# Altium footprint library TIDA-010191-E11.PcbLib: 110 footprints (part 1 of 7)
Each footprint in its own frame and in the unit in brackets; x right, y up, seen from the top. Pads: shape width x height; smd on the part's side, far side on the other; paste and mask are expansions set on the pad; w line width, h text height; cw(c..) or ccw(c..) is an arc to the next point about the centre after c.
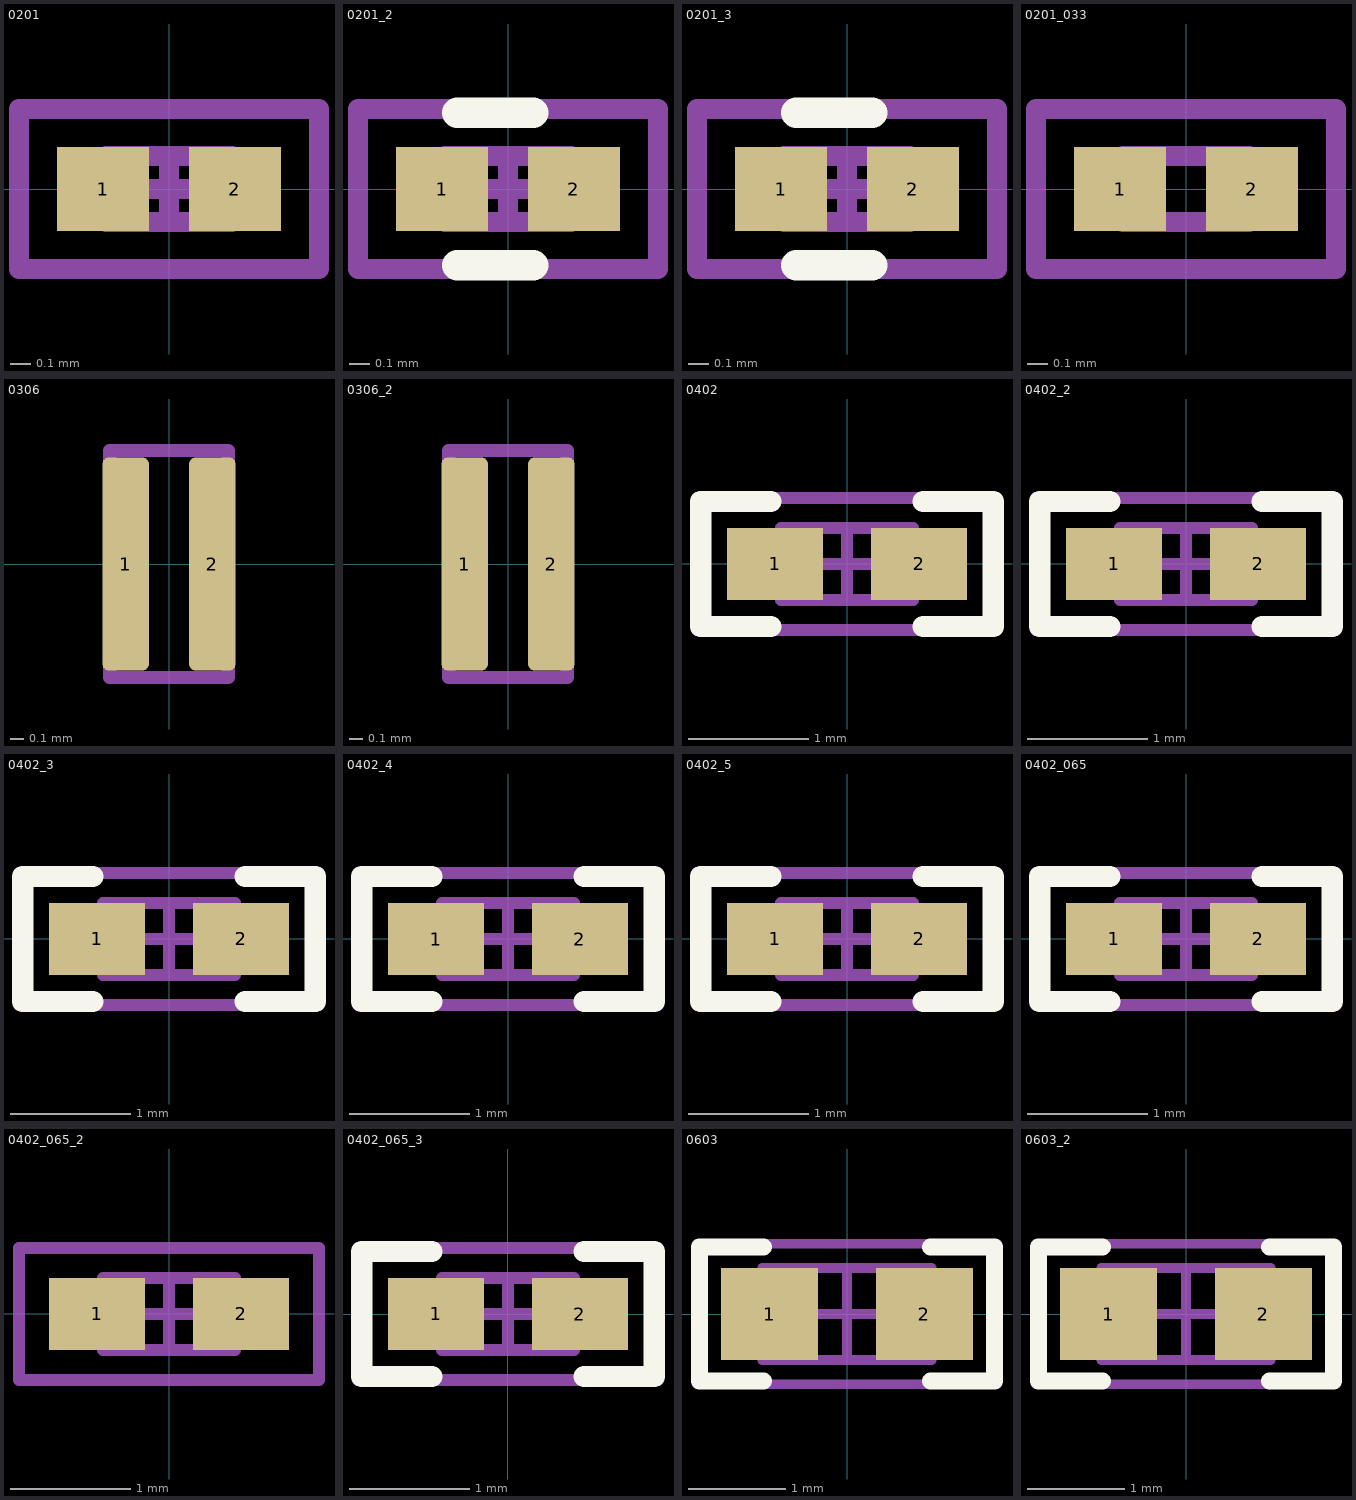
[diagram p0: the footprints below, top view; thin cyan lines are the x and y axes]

## 0201 [mm] "Data from Kemet datasheet CC101_COM dated 7/28/11"
height 0.26
pads (2):
  rect 0.46x0.42 smd mask+0.048: 1(-0.33,0) 2(0.33,0)
Mechanical 5:
  lines w0.1: -0.75,-0.4 -0.75,0.4 0.75,0.4 0.75,-0.4 -0.75,-0.4
  text ".Designator" at -0.66,-0.178 h0.36
Mechanical 13:
  lines w0.1: -0.215,-0.165 -0.215,0.165 ; 0.215,-0.165 0.215,0.165 ; -0.315,-0.165 0.315,-0.165 0.315,0.165 -0.315,0.165 -0.315,-0.165
Mechanical 15:
  lines w0.1: -0.165,0 0.165,0 ; 0,-0.165 0,0.165 ; -0.75,-0.4 0.75,-0.4 0.75,0.4 -0.75,0.4 -0.75,-0.4
3D body: height 0.26, standoff 0, extent 0.216,-0.164 0.314,0.164
3D body: height 0.26, standoff 0, extent -0.214,-0.164 0.214,0.164
3D body: height 0.26, standoff 0, extent -0.314,-0.164 -0.216,0.164

## 0201_2 [mm]
pads (2):
  rect 0.46x0.42 smd mask+0.048: 1(-0.33,0) 2(0.33,0)
Top Overlay:
  lines w0.152: -0.254,-0.381 0.127,-0.381 ; -0.254,0.381 0.127,0.381
Mechanical 5:
  lines w0.1: -0.75,-0.4 0.75,-0.4 0.75,0.4 -0.75,0.4 -0.75,-0.4
  text ".Designator" at 0.736,1.236 h0.64
Mechanical 13:
  lines w0.1: -0.215,-0.165 -0.215,0.165 ; 0.215,-0.165 0.215,0.165 ; -0.315,-0.165 -0.315,0.165 0.315,0.165 0.315,-0.165 -0.315,-0.165
Mechanical 15:
  lines w0.1: -0.165,0 0.165,0 ; 0,-0.165 0,0.165 ; -0.75,-0.4 -0.75,0.4 0.75,0.4 0.75,-0.4 -0.75,-0.4
3D body: height 0.26, standoff 0, extent -0.314,-0.164 -0.216,0.164
3D body: height 0.26, standoff 0, extent -0.214,-0.164 0.214,0.164
3D body: height 0.26, standoff 0, extent 0.216,-0.164 0.314,0.164

## 0201_3 [mm]
pads (2):
  rect 0.46x0.42 smd mask+0.048: 1(-0.33,0) 2(0.33,0)
Top Overlay:
  lines w0.152: -0.254,-0.381 0.127,-0.381 ; -0.254,0.381 0.127,0.381
Mechanical 5:
  lines w0.1: -0.75,-0.4 0.75,-0.4 0.75,0.4 -0.75,0.4 -0.75,-0.4
  text ".Designator" at -2.175,-0.278 h0.64
Mechanical 13:
  lines w0.1: -0.215,-0.165 -0.215,0.165 ; 0.215,-0.165 0.215,0.165 ; -0.315,-0.165 -0.315,0.165 0.315,0.165 0.315,-0.165 -0.315,-0.165
Mechanical 15:
  lines w0.1: -0.165,0 0.165,0 ; 0,-0.165 0,0.165 ; -0.75,-0.4 -0.75,0.4 0.75,0.4 0.75,-0.4 -0.75,-0.4
3D body: height 0.26, standoff 0, extent -0.314,-0.164 -0.216,0.164
3D body: height 0.26, standoff 0, extent -0.214,-0.164 0.214,0.164
3D body: height 0.26, standoff 0, extent 0.216,-0.164 0.314,0.164

## 0201_033 [mm] "SMD, 2-Leads, Height 0.33mm"
height 0.33
pads (2):
  rect 0.46x0.42 smd mask+0.048: 1(-0.33,0) 2(0.33,0)
Mechanical 5:
  lines w0.1: -0.75,-0.4 0.75,-0.4 0.75,0.4 -0.75,0.4 -0.75,-0.4
  text ".Designator" at -2.035,-0.307 h0.64
Mechanical 13:
  lines w0.1: -0.215,-0.165 -0.215,0.165 ; 0.215,-0.165 0.215,0.165 ; -0.315,-0.165 -0.315,0.165 0.315,0.165 0.315,-0.165 -0.315,-0.165
3D body: height 0.33, standoff 0, extent -0.314,-0.164 -0.216,0.164
3D body: height 0.33, standoff 0, extent -0.214,-0.164 0.214,0.164
3D body: height 0.33, standoff 0, extent 0.216,-0.164 0.314,0.164

## 0306 [mm] "based on TDK recommendation (similar to Taiyo Yuden and MuRata)"
height 0.6
pads (2):
  rrect29% 0.35x1.6 smd: 1(-0.325,0) 2(0.325,0)
Mechanical 5:
  lines w0.1: -0.241,-0.851 -0.445,-0.851 ; -0.241,0.851 -0.445,0.851 ; 0.241,-0.851 0.445,-0.851 ; 0.241,0.851 0.445,0.851 ; -0.445,-0.851 -0.445,0.851 ; -0.445,-0.851 0.445,-0.851 ; -0.445,-0.851 -0.445,0.851 ; -0.445,0.851 0.445,0.851 ; 0.445,-0.851 0.445,0.851 ; 0.445,-0.851 0.445,0.851
  text ".Designator" at -0.2,0.7 h0.38
3D body: height 0.6, standoff 0, extent 0.242,-0.85 0.444,0.85
3D body: height 0.6, standoff 0, extent -0.241,-0.85 0.241,0.85
3D body: height 0.6, standoff 0, extent -0.444,-0.85 -0.242,0.85

## 0306_2 [mm]
pads (2):
  rrect29% 0.35x1.6 smd: 1(-0.325,0) 2(0.325,0)
Mechanical 5:
  lines w0.1: -0.241,-0.851 -0.445,-0.851 ; -0.241,0.851 -0.445,0.851 ; 0.241,-0.851 0.445,-0.851 ; 0.241,0.851 0.445,0.851 ; -0.445,-0.851 -0.445,0.851 ; -0.445,-0.851 0.445,-0.851 ; -0.445,-0.851 -0.445,0.851 ; -0.445,0.851 0.445,0.851 ; 0.445,-0.851 0.445,0.851 ; 0.445,-0.851 0.445,0.851
  text ".Designator" at -0.2,0.7 h0.38
3D body: height 0.6, standoff 0, extent 0.242,-0.85 0.444,0.85
3D body: height 0.6, standoff 0, extent -0.241,-0.85 0.241,0.85
3D body: height 0.6, standoff 0, extent -0.444,-0.85 -0.242,0.85

## 0402 [mm] "0402 from SM-752 data"
height 0.6
pads (2):
  rect 0.8x0.6 smd: 1(-0.6,0) 2(0.6,0)
Top Overlay:
  lines w0.178: -0.635,-0.521 -1.219,-0.521 -1.219,0.521 -0.635,0.521 ; 0.635,-0.521 1.219,-0.521 1.219,0.521 0.635,0.521
Mechanical 5:
  lines w0.1: -1.25,-0.55 -1.25,0.55 1.25,0.55 1.25,-0.55 -1.25,-0.55
  text ".Designator" at -1.117,-0.305 h0.61
Mechanical 13:
  lines w0.1: -0.35,-0.3 -0.35,0.3 ; 0.35,-0.3 0.35,0.3 ; -0.55,-0.3 0.55,-0.3 0.55,0.3 -0.55,0.3 -0.55,-0.3
Mechanical 15:
  lines w0.1: -0.3,0 0.3,0 ; 0,-0.3 0,0.3 ; -1.25,-0.55 1.25,-0.55 1.25,0.55 -1.25,0.55 -1.25,-0.55
3D body: height 0.6, standoff 0, extent 0.351,-0.299 0.549,0.299
3D body: height 0.6, standoff 0, extent -0.349,-0.299 0.349,0.299
3D body: height 0.6, standoff 0, extent -0.549,-0.299 -0.351,0.299

## 0402_2 [mm]
pads (2):
  rect 0.8x0.6 smd: 1(-0.6,0) 2(0.6,0)
Top Overlay:
  lines w0.178: -0.635,-0.521 -1.219,-0.521 -1.219,0.521 -0.635,0.521 ; 0.635,-0.521 1.219,-0.521 1.219,0.521 0.635,0.521
Mechanical 5:
  lines w0.1: -1.25,-0.55 -1.25,0.55 1.25,0.55 1.25,-0.55 -1.25,-0.55
  text ".Designator" at -1.117,-0.305 h0.61
Mechanical 13:
  lines w0.1: -0.35,-0.3 -0.35,0.3 ; 0.35,-0.3 0.35,0.3 ; -0.55,-0.3 0.55,-0.3 0.55,0.3 -0.55,0.3 -0.55,-0.3
Mechanical 15:
  lines w0.1: -0.3,0 0.3,0 ; 0,-0.3 0,0.3 ; -1.25,-0.55 1.25,-0.55 1.25,0.55 -1.25,0.55 -1.25,-0.55
3D body: height 0.6, standoff 0, extent 0.351,-0.299 0.549,0.299
3D body: height 0.6, standoff 0, extent -0.349,-0.299 0.349,0.299
3D body: height 0.6, standoff 0, extent -0.549,-0.299 -0.351,0.299

## 0402_3 [mm]
pads (2):
  rect 0.8x0.6 smd: 1(-0.6,0) 2(0.6,0)
Top Overlay:
  lines w0.178: -0.635,-0.521 -1.219,-0.521 -1.219,0.521 -0.635,0.521 ; 0.635,-0.521 1.219,-0.521 1.219,0.521 0.635,0.521
Mechanical 5:
  lines w0.1: -1.25,-0.55 1.25,-0.55 1.25,0.55 -1.25,0.55 -1.25,-0.55
  text ".Designator" at -1.117,-0.305 h0.61
Mechanical 13:
  lines w0.1: -0.35,-0.3 -0.35,0.3 ; 0.35,-0.3 0.35,0.3 ; -0.55,-0.3 -0.55,0.3 0.55,0.3 0.55,-0.3 -0.55,-0.3
Mechanical 15:
  lines w0.1: -0.3,0 0.3,0 ; 0,-0.3 0,0.3 ; -1.25,-0.55 -1.25,0.55 1.25,0.55 1.25,-0.55 -1.25,-0.55
3D body: height 0.6, standoff 0, extent -0.549,-0.299 -0.351,0.299
3D body: height 0.6, standoff 0, extent -0.349,-0.299 0.349,0.299
3D body: height 0.6, standoff 0, extent 0.351,-0.299 0.549,0.299

## 0402_4 [mm]
pads (2):
  rect 0.8x0.6 smd: 1(-0.6,0) 2(0.6,0)
Top Overlay:
  lines w0.178: -0.635,-0.521 -1.219,-0.521 -1.219,0.521 -0.635,0.521 ; 0.635,-0.521 1.219,-0.521 1.219,0.521 0.635,0.521
Mechanical 5:
  lines w0.1: -1.25,-0.55 -1.25,0.55 1.25,0.55 1.25,-0.55 -1.25,-0.55
  text ".Designator" at 1.025,-0.845 h0.64
Mechanical 13:
  lines w0.1: -0.35,-0.3 -0.35,0.3 ; 0.35,-0.3 0.35,0.3 ; -0.55,-0.3 0.55,-0.3 0.55,0.3 -0.55,0.3 -0.55,-0.3
Mechanical 15:
  lines w0.1: -0.3,0 0.3,0 ; 0,-0.3 0,0.3 ; -1.25,-0.55 1.25,-0.55 1.25,0.55 -1.25,0.55 -1.25,-0.55
3D body: height 0.6, standoff 0, extent 0.351,-0.299 0.549,0.299
3D body: height 0.6, standoff 0, extent -0.349,-0.299 0.349,0.299
3D body: height 0.6, standoff 0, extent -0.549,-0.299 -0.351,0.299

## 0402_5 [mm]
pads (2):
  rect 0.8x0.6 smd: 1(-0.6,0) 2(0.6,0)
Top Overlay:
  lines w0.178: -0.635,-0.521 -1.219,-0.521 -1.219,0.521 -0.635,0.521 ; 0.635,-0.521 1.219,-0.521 1.219,0.521 0.635,0.521
Mechanical 5:
  lines w0.1: -1.25,-0.55 -1.25,0.55 1.25,0.55 1.25,-0.55 -1.25,-0.55
  text ".Designator" at -1.168,-1.457 h0.64
Mechanical 13:
  lines w0.1: -0.35,-0.3 -0.35,0.3 ; 0.35,-0.3 0.35,0.3 ; -0.55,-0.3 0.55,-0.3 0.55,0.3 -0.55,0.3 -0.55,-0.3
Mechanical 15:
  lines w0.1: -0.3,0 0.3,0 ; 0,-0.3 0,0.3 ; -1.25,-0.55 1.25,-0.55 1.25,0.55 -1.25,0.55 -1.25,-0.55
3D body: height 0.6, standoff 0, extent 0.351,-0.299 0.549,0.299
3D body: height 0.6, standoff 0, extent -0.349,-0.299 0.349,0.299
3D body: height 0.6, standoff 0, extent -0.549,-0.299 -0.351,0.299

## 0402_065 [mm] "0402"
height 0.65
pads (2):
  rect 0.8x0.6 smd: 1(-0.6,0) 2(0.6,0)
Top Overlay:
  lines w0.178: -0.635,-0.521 -1.219,-0.521 -1.219,0.521 -0.635,0.521 ; 0.635,-0.521 1.219,-0.521 1.219,0.521 0.635,0.521
Mechanical 5:
  lines w0.1: -1.25,-0.55 1.25,-0.55 1.25,0.55 -1.25,0.55 -1.25,-0.55
  text ".Designator" at -1.117,-0.305 h0.61
Mechanical 13:
  lines w0.1: -0.35,-0.3 -0.35,0.3 ; 0.35,-0.3 0.35,0.3 ; -0.55,-0.3 -0.55,0.3 0.55,0.3 0.55,-0.3 -0.55,-0.3
Mechanical 15:
  lines w0.1: -0.3,0 0.3,0 ; 0,-0.3 0,0.3 ; -1.25,-0.55 -1.25,0.55 1.25,0.55 1.25,-0.55 -1.25,-0.55
3D body: height 0.65, standoff 0, extent -0.549,-0.299 -0.351,0.299
3D body: height 0.65, standoff 0, extent -0.349,-0.299 0.349,0.299
3D body: height 0.65, standoff 0, extent 0.351,-0.299 0.549,0.299

## 0402_065_2 [mm]
pads (2):
  rect 0.8x0.6 smd: 1(-0.6,0) 2(0.6,0)
Mechanical 5:
  lines w0.1: -1.25,-0.55 1.25,-0.55 1.25,0.55 -1.25,0.55 -1.25,-0.55
  text ".Designator" at 1.487,-0.253 h0.64
Mechanical 13:
  lines w0.1: -0.35,-0.3 -0.35,0.3 ; 0.35,-0.3 0.35,0.3 ; -0.55,-0.3 -0.55,0.3 0.55,0.3 0.55,-0.3 -0.55,-0.3
Mechanical 15:
  lines w0.1: -0.3,0 0.3,0 ; 0,-0.3 0,0.3 ; -1.25,-0.55 -1.25,0.55 1.25,0.55 1.25,-0.55 -1.25,-0.55
3D body: height 0.65, standoff 0, extent -0.549,-0.299 -0.351,0.299
3D body: height 0.65, standoff 0, extent -0.349,-0.299 0.349,0.299
3D body: height 0.65, standoff 0, extent 0.351,-0.299 0.549,0.299

## 0402_065_3 [mm]
pads (2):
  rect 0.8x0.6 smd: 1(-0.6,0) 2(0.6,0)
Top Overlay:
  lines w0.178: -0.635,-0.521 -1.219,-0.521 -1.219,0.521 -0.635,0.521 ; 0.635,-0.521 1.219,-0.521 1.219,0.521 0.635,0.521
Mechanical 5:
  lines w0.1: -1.25,-0.55 1.25,-0.55 1.25,0.55 -1.25,0.55 -1.25,-0.55
  text ".Designator" at -0.892,-0.317 h0.64
Mechanical 13:
  lines w0.1: -0.35,-0.3 -0.35,0.3 ; 0.35,-0.3 0.35,0.3 ; -0.55,-0.3 -0.55,0.3 0.55,0.3 0.55,-0.3 -0.55,-0.3
Mechanical 15:
  lines w0.1: -0.3,0 0.3,0 ; 0,-0.3 0,0.3 ; -1.25,-0.55 -1.25,0.55 1.25,0.55 1.25,-0.55 -1.25,-0.55
3D body: height 0.65, standoff 0, extent -0.549,-0.299 -0.351,0.299
3D body: height 0.65, standoff 0, extent -0.349,-0.299 0.349,0.299
3D body: height 0.65, standoff 0, extent 0.351,-0.299 0.549,0.299

## 0603 [mm] "0603 from SM-752 data"
height 1
pads (2):
  rect 1x0.95 smd: 1(-0.8,0) 2(0.8,0)
Top Overlay:
  lines w0.178: -0.864,-0.691 -1.524,-0.691 -1.524,0.693 -0.864,0.693 ; 0.864,-0.691 1.524,-0.691 1.524,0.693 0.864,0.693
Mechanical 5:
  lines w0.1: -1.55,-0.725 1.55,-0.725 1.55,0.725 -1.55,0.725 -1.55,-0.725
  text ".Designator" at -1.397,-0.381 h0.76
Mechanical 13:
  lines w0.1: -0.55,-0.475 -0.55,0.475 ; 0.55,-0.475 0.55,0.475 ; -0.875,-0.475 -0.875,0.475 0.875,0.475 0.875,-0.475 -0.875,-0.475
Mechanical 15:
  lines w0.1: -0.475,0 0.475,0 ; 0,-0.475 0,0.475 ; -1.55,-0.725 -1.55,0.725 1.55,0.725 1.55,-0.725 -1.55,-0.725
3D body: height 1, standoff 0, extent 0.551,-0.474 0.874,0.474
3D body: height 1, standoff 0, extent -0.549,-0.474 0.549,0.474
3D body: height 1, standoff 0, extent -0.874,-0.474 -0.551,0.474

## 0603_2 [mm]
pads (2):
  rect 1x0.95 smd: 1(-0.8,0) 2(0.8,0)
Top Overlay:
  lines w0.178: -0.864,-0.691 -1.524,-0.691 -1.524,0.693 -0.864,0.693 ; 0.864,-0.691 1.524,-0.691 1.524,0.693 0.864,0.693
Mechanical 5:
  lines w0.1: -1.55,-0.725 -1.55,0.725 1.55,0.725 1.55,-0.725 -1.55,-0.725
  text ".Designator" at -1.397,-0.381 h0.76
Mechanical 13:
  lines w0.1: -0.55,-0.475 -0.55,0.475 ; 0.55,-0.475 0.55,0.475 ; -0.875,-0.475 0.875,-0.475 0.875,0.475 -0.875,0.475 -0.875,-0.475
Mechanical 15:
  lines w0.1: -0.475,0 0.475,0 ; 0,-0.475 0,0.475 ; -1.55,-0.725 1.55,-0.725 1.55,0.725 -1.55,0.725 -1.55,-0.725
3D body: height 1, standoff 0, extent -0.874,-0.474 -0.551,0.474
3D body: height 1, standoff 0, extent -0.549,-0.474 0.549,0.474
3D body: height 1, standoff 0, extent 0.551,-0.474 0.874,0.474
